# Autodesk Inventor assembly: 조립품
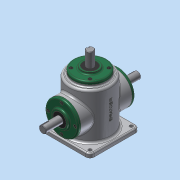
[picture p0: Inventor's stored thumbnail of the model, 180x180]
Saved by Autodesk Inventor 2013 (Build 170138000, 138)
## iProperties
Created: 2015-10
Part Number: 조립품
Document SubType Name: Assembly
Designer: ST4
Author: ST4
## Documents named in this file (14)
- C:\Users\ST4\Desktop\451007V1004\조립품.iam
- C:\Users\ST4\Desktop\451007V1004\M4.ipt
- C:\Users\ST4\Desktop\451007V1004\메인 베벨기어.ipt
- C:\Users\ST4\Desktop\451007V1004\메인 축.ipt
- 메인 축.ipt
- C:\Users\ST4\Desktop\451007V1004\베어링 6203.ipt
- C:\Users\ST4\Desktop\451007V1004\본체.ipt
- C:\Users\ST4\Desktop\451007V1004\서브 베벨기어.ipt
- C:\Users\ST4\Desktop\451007V1004\서브 축.ipt
- 서브 축.ipt
- C:\Users\ST4\Desktop\451007V1004\오일실.ipt
- C:\Users\ST4\Desktop\451007V1004\커버.ipt
- C:\Users\ST4\Desktop\451007V1004\키 4x4.ipt
- C:\Users\ST4\Desktop\451007V1004\키 5x5.ipt
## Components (12 placed, 1 different names)
1. M4:1
2. M4:2
3. M4:3
4. M4:4
5. M4:6
6. M4:7
7. M4:8
8. M4:9
9. M4:5
10. M4:10
11. M4:11
12. M4:12
